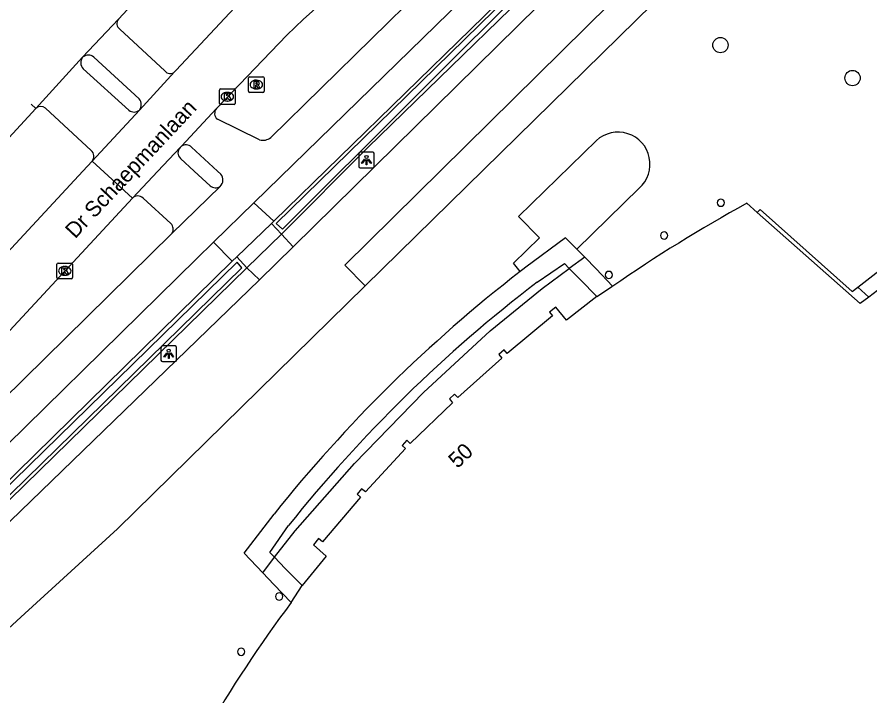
# Model space of a CAD drawing. Extents: x 161402 to 161933, y 381650 to 382313.
# Drawn here: x 161733.4 to 161787.9, y 382216.4 to 382259.8 of the extents above; entities that cross this region are included whole.
import ezdxf

# ---------------------------------------------------------------- set-up
doc = ezdxf.new("R2010")
doc.units = 0
for name, color, linetype in [('IMGEO_Boom', 7, 'Continuous'), ('IMGEO_Fietspad_open', 7, 'Continuous'), ('IMGEO_Kolk', 7, 'Continuous'), ('IMGEO_Lichtpunt', 7, 'Continuous'), ('IMGEO_Muur', 7, 'Continuous'), ('IMGEO_Openbare_ruimte_label', 7, 'Continuous'), ('IMGEO_Pand', 7, 'Continuous'), ('IMGEO_Pand_nummerreeks', 7, 'Continuous'), ('IMGEO_Rijbaan_lokaal_gesloten', 7, 'Continuous'), ('IMGEO_Rijbaan_lokaal_open', 7, 'Continuous'), ('IMGEO_Rioolput', 7, 'Continuous'), ('IMGEO_Voetpad_gesloten', 7, 'Continuous'), ('IMGEO_Voetpad_open', 7, 'Continuous')]:
    doc.layers.add(name, color=color, linetype=linetype)

msp = doc.modelspace()

# ---------------------------------------------------------------- linework, layer by layer
at = {"layer": 'IMGEO_Boom'}
for centre in [(161778.302, 382258.047), (161786.74, 382255.943)]:
    msp.add_circle(centre, 0.489, dxfattribs=at)
at = {"layer": 'IMGEO_Fietspad_open'}
for points in [[(161762.43, 382264.784), (161749.565, 382252.142)], [(161748.486, 382247.967), (161765.113, 382264.207)], [(161739.929, 382259.066), (161742.796, 382256.396)], [(161741.158, 382254.603), (161738.265, 382257.28)], [(161748.853, 382251.989), (161746.158, 382253.319)], [(161744.502, 382251.534), (161746.159, 382250), (161746.382, 382249.794)], [(161746.337, 382249.017), (161743.258, 382246.014)], [(161745.906, 382245.446), (161748.486, 382247.967)], [(161743.258, 382246.014), (161728.369, 382231.371), (161727.383, 382230.373), (161709.873, 382209.811)], [(161711.467, 382208.182), (161729.058, 382228.913), (161744.819, 382244.379), (161745.906, 382245.446)]]:
    msp.add_lwpolyline(points, dxfattribs=at)
for centre, radius, start, end in [((161740.169, 382259.426), 0.433, 140.7167, 236.3271), ((161737.915, 382256.852), 0.553, 50.7037, 131.3767), ((161743.142, 382256.687), 0.453, 220.082, 308.6592), ((161740.743, 382254.236), 0.555, 321.7237, 41.4988), ((161746.452, 382253.683), 0.468, 139.3618, 231.058), ((161749.059, 382252.765), 0.802, 255.1413, 309.1142), ((161744.154, 382251.15), 0.518, 47.7745, 123.7726), ((161745.956, 382249.429), 0.561, 312.7967, 40.5741)]:
    msp.add_arc(centre, radius, start, end, dxfattribs=at)
at = {"layer": 'IMGEO_Kolk'}
for p, q in [((161746.297, 382254.32), (161746.297, 382255.172)), ((161746.372, 382255.246), (161747.224, 382255.246)), ((161746.785, 382255.026), (161746.81, 382255.026)), ((161747.298, 382255.172), (161747.298, 382254.32)), ((161746.808, 382254.466), (161746.783, 382254.466)), ((161747.224, 382254.246), (161746.372, 382254.246)), ((161735.911, 382243.191), (161735.911, 382244.043)), ((161735.986, 382244.117), (161736.838, 382244.117)), ((161736.912, 382244.043), (161736.912, 382243.191)), ((161736.399, 382243.897), (161736.424, 382243.897)), ((161736.838, 382243.117), (161735.986, 382243.117)), ((161736.422, 382243.337), (161736.397, 382243.337))]:
    msp.add_line(p, q, dxfattribs=at)
for points in [[(161746.297, 382254.32), (161746.297, 382255.172)], [(161746.372, 382255.246), (161747.224, 382255.246)], [(161746.618, 382254.946), (161746.741, 382254.946), (161746.741, 382254.795), (161746.871, 382254.946), (161747.035, 382254.946), (161746.889, 382254.795), (161747.042, 382254.546), (161746.89, 382254.546), (161746.805, 382254.71), (161746.741, 382254.643), (161746.741, 382254.546), (161746.618, 382254.546), (161746.618, 382254.946)], [(161747.298, 382255.172), (161747.298, 382254.32)], [(161747.224, 382254.246), (161746.372, 382254.246)], [(161735.911, 382243.191), (161735.911, 382244.043)], [(161735.986, 382244.117), (161736.838, 382244.117)], [(161736.912, 382244.043), (161736.912, 382243.191)], [(161736.232, 382243.817), (161736.355, 382243.817), (161736.355, 382243.666), (161736.485, 382243.817), (161736.649, 382243.817), (161736.503, 382243.666), (161736.656, 382243.417), (161736.504, 382243.417), (161736.419, 382243.581), (161736.355, 382243.514), (161736.355, 382243.417), (161736.232, 382243.417), (161736.232, 382243.817)], [(161736.838, 382243.117), (161735.986, 382243.117)]]:
    msp.add_lwpolyline(points, dxfattribs=at)
for centre, start, end in [((161746.374, 382255.17), 91.552, 178.448), ((161746.374, 382255.17), 91.552, 178.448), ((161747.222, 382255.17), 1.552, 88.448), ((161747.222, 382255.17), 1.552, 88.448), ((161746.374, 382254.322), 181.552, 268.448), ((161746.374, 382254.322), 181.552, 268.448), ((161747.222, 382254.322), 271.552, 358.448), ((161747.222, 382254.322), 271.552, 358.448), ((161735.988, 382244.041), 91.552, 178.448), ((161735.988, 382244.041), 91.552, 178.448), ((161736.836, 382244.041), 1.552, 88.448), ((161736.836, 382244.041), 1.552, 88.448), ((161735.988, 382243.193), 181.552, 268.448), ((161735.988, 382243.193), 181.552, 268.448), ((161736.836, 382243.193), 271.552, 358.448), ((161736.836, 382243.193), 271.552, 358.448)]:
    msp.add_arc(centre, 0.0765, start, end, dxfattribs=at)
for centre, major_axis, ratio, start_param, end_param in [((161746.784, 382254.746), (-0.387, 0.002), 0.722429, 4.712389, 7.853982), ((161746.809, 382254.746), (-0.39, 0.002), 0.717154, 1.570796, 4.712389), ((161736.398, 382243.617), (-0.387, 0.002), 0.722429, 4.712389, 7.853982), ((161736.423, 382243.617), (-0.39, 0.002), 0.717154, 1.570796, 4.712389)]:
    msp.add_ellipse(centre, major_axis=major_axis, ratio=ratio, start_param=start_param, end_param=end_param, dxfattribs=at)
at = {"layer": 'IMGEO_Lichtpunt'}
for p, q in [((161755.191, 382251.099), (161755.191, 382250.292)), ((161755.191, 382251.099), (161755.191, 382250.292)), ((161756.093, 382251.194), (161755.285, 382251.194)), ((161756.093, 382251.194), (161755.285, 382251.194)), ((161756.187, 382250.292), (161756.187, 382251.099)), ((161756.187, 382250.292), (161756.187, 382251.099)), ((161755.285, 382250.198), (161756.093, 382250.198)), ((161755.285, 382250.198), (161756.093, 382250.198)), ((161742.554, 382238.724), (161742.554, 382237.917)), ((161742.554, 382238.724), (161742.554, 382237.917)), ((161743.456, 382238.819), (161742.648, 382238.819)), ((161743.456, 382238.819), (161742.648, 382238.819)), ((161743.55, 382237.917), (161743.55, 382238.724)), ((161743.55, 382237.917), (161743.55, 382238.724)), ((161742.648, 382237.823), (161743.456, 382237.823)), ((161742.648, 382237.823), (161743.456, 382237.823))]:
    msp.add_line(p, q, dxfattribs=at)
for points in [[(161755.565, 382250.763), (161755.604, 382250.735), (161755.416, 382250.473), (161755.378, 382250.5), (161755.565, 382250.763)], [(161755.667, 382250.715), (161755.714, 382250.715), (161755.714, 382250.393), (161755.667, 382250.393), (161755.667, 382250.715)], [(161755.777, 382250.735), (161755.815, 382250.762), (161756.002, 382250.5), (161755.963, 382250.472), (161755.777, 382250.735)], [(161742.928, 382238.388), (161742.967, 382238.36), (161742.779, 382238.098), (161742.741, 382238.125), (161742.928, 382238.388)], [(161743.03, 382238.34), (161743.077, 382238.34), (161743.077, 382238.018), (161743.03, 382238.018), (161743.03, 382238.34)], [(161743.14, 382238.36), (161743.178, 382238.387), (161743.365, 382238.125), (161743.326, 382238.097), (161743.14, 382238.36)]]:
    msp.add_lwpolyline(points, dxfattribs=at)
for centre in [(161755.69, 382250.897), (161743.053, 382238.522)]:
    msp.add_circle(centre, 0.0994, dxfattribs=at)
for centre, start, end in [((161755.285, 382251.099), 90, 180), ((161755.285, 382251.099), 90, 180), ((161756.093, 382251.099), 0, 90), ((161756.093, 382251.099), 0, 90), ((161755.285, 382250.292), 180, 270), ((161755.285, 382250.292), 180, 270), ((161756.093, 382250.292), 270, 0), ((161756.093, 382250.292), 270, 360), ((161742.648, 382238.724), 90, 180), ((161742.648, 382238.724), 90, 180), ((161743.456, 382238.724), 0, 90), ((161743.456, 382238.724), 0, 90), ((161742.648, 382237.917), 180, 270), ((161742.648, 382237.917), 180, 270), ((161743.456, 382237.917), 270, 0), ((161743.456, 382237.917), 270, 360)]:
    msp.add_arc(centre, 0.0946, start, end, dxfattribs=at)
at = {"layer": 'IMGEO_Muur'}
for points in [[(161749.768, 382246.799), (161766.553, 382263.178), (161766.895, 382262.953), (161769.85, 382265.834), (161770.184, 382265.542), (161755.779, 382251.492), (161750.251, 382245.958)], [(161750.317, 382246.283), (161766.834, 382262.773), (161766.612, 382262.991), (161749.919, 382246.636), (161750.317, 382246.283)], [(161749.616, 382246.65), (161749.768, 382246.799)], [(161750.251, 382245.958), (161749.616, 382246.65)], [(161747.1, 382244.24), (161747.399, 382244.517)], [(161747.399, 382244.517), (161748.046, 382243.815)], [(161748.046, 382243.815), (161715.85, 382212.342), (161715.57, 382212.632), (161719.892, 382216.863), (161719.584, 382217.248), (161747.1, 382244.24)], [(161720.173, 382216.864), (161747.726, 382243.82), (161747.429, 382244.182), (161719.85, 382217.217), (161720.173, 382216.864)]]:
    msp.add_lwpolyline(points, dxfattribs=at)
at = {"layer": 'IMGEO_Pand'}
for points in [[(161779.989, 382247.938), (161780.646, 382247.356)], [(161787.788, 382241.947), (161787.231, 382241.522), (161780.646, 382247.356)], [(161795.694, 382238.808), (161794.961, 382238.384), (161795.219, 382237.93), (161794.18, 382236.915), (161789.097, 382243.778), (161788.496, 382243.19), (161788.889, 382242.788), (161787.788, 382241.947)], [(161770.405, 382241.973), (161771.415, 382242.629)], [(161770.405, 382241.973), (161768.459, 382240.475), (161767.778, 382241.294), (161767.375, 382240.978), (161767.578, 382240.738), (161764.683, 382238.344), (161764.488, 382238.566), (161764.134, 382238.278), (161764.331, 382238.028), (161761.527, 382235.526), (161761.314, 382235.737), (161760.988, 382235.435), (161761.183, 382235.183), (161758.474, 382232.588), (161758.255, 382232.795), (161757.969, 382232.452), (161758.183, 382232.257), (161755.627, 382229.489), (161755.369, 382229.691), (161755.085, 382229.339), (161755.299, 382229.159), (161752.877, 382226.292), (161752.611, 382226.516), (161752.291, 382226.105), (161753.12, 382225.389), (161751.568, 382223.506)], [(161750.883, 382222.424), (161751.568, 382223.506)]]:
    msp.add_lwpolyline(points, dxfattribs=at)
for centre, radius, start, end in [((161825.854, 382164.289), 95.398, 118.73588, 124.7955), ((161778.325, 382247.974), 0.23, 90, 270), ((161778.325, 382247.974), 0.23, 270, 90), ((161774.702, 382245.879), 0.23, 90, 270), ((161774.702, 382245.879), 0.23, 270, 90), ((161771.17, 382243.355), 0.23, 90, 270), ((161771.17, 382243.355), 0.23, 270, 90), ((161750.105, 382222.803), 0.23, 90, 270), ((161750.105, 382222.803), 0.23, 270, 90), ((161816.968, 382172.845), 82.616, 143.12172, 150.09585), ((161747.682, 382219.274), 0.23, 90, 270), ((161747.682, 382219.274), 0.23, 270, 90)]:
    msp.add_arc(centre, radius, start, end, dxfattribs=at)
at = {"layer": 'IMGEO_Rijbaan_lokaal_gesloten'}
for points in [[(161739.834, 382259.7), (161744.067, 382264.267), (161744.269, 382264.464)], [(161747.864, 382261.109), (161743.521, 382256.439), (161743.425, 382256.334)], [(161737.549, 382257.267), (161739.834, 382259.7)], [(161734.565, 382254.001), (161737.549, 382257.267)], [(161746.097, 382253.988), (161749.055, 382257.09)], [(161743.425, 382256.334), (161741.178, 382253.892)], [(161697.412, 382213.802), (161730.864, 382250), (161734.565, 382254.001)], [(161734.565, 382254.001), (161734.265, 382254.268)], [(161741.178, 382253.892), (161738.153, 382250.632)], [(161743.866, 382251.581), (161746.097, 382253.988)], [(161740.731, 382248.263), (161742.363, 382250), (161743.776, 382251.504)], [(161743.776, 382251.504), (161743.866, 382251.581)], [(161738.153, 382250.632), (161737.568, 382250), (161701.048, 382210.574)], [(161738.153, 382250.632), (161740.731, 382248.263)], [(161709.017, 382214.078), (161740.731, 382248.263)]]:
    msp.add_lwpolyline(points, dxfattribs=at)
msp.add_arc((161792.83, 382215.895), 60.111, 114.26707, 136.73891, dxfattribs=at)
at = {"layer": 'IMGEO_Rijbaan_lokaal_open'}
for points in [[(161777.222, 382263.881), (161775.857, 382265.264), (161754.297, 382243.989), (161755.602, 382242.666)], [(161766.659, 382260.549), (161751.001, 382245.149)], [(161751.001, 382245.149), (161748.845, 382243.038)], [(161748.845, 382243.038), (161728.253, 382223.117), (161713.169, 382208.748), (161711.914, 382207.765)], [(161755.602, 382242.666), (161739.772, 382227.133), (161733.859, 382221.725), (161710.972, 382200.713)]]:
    msp.add_lwpolyline(points, dxfattribs=at)
at = {"layer": 'IMGEO_Rioolput'}
for p, q in [((161748.145, 382255.099), (161748.145, 382255.951)), ((161748.22, 382256.025), (161749.072, 382256.025)), ((161749.146, 382255.951), (161749.146, 382255.099)), ((161748.633, 382255.805), (161748.658, 382255.805)), ((161749.072, 382255.025), (161748.22, 382255.025)), ((161748.656, 382255.245), (161748.631, 382255.245))]:
    msp.add_line(p, q, dxfattribs=at)
for points in [[(161748.145, 382255.099), (161748.145, 382255.951)], [(161748.22, 382256.025), (161749.072, 382256.025)], [(161749.146, 382255.951), (161749.146, 382255.099)], [(161748.734, 382255.723), (161748.482, 382255.725), (161748.482, 382255.325)], [(161748.482, 382255.325), (161748.606, 382255.325), (161748.606, 382255.487), (161748.617, 382255.487)], [(161748.66, 382255.644), (161748.606, 382255.644), (161748.606, 382255.563)], [(161748.606, 382255.563), (161748.658, 382255.563)], [(161748.664, 382255.458), (161748.735, 382255.325), (161748.875, 382255.325), (161748.81, 382255.451)], [(161749.072, 382255.025), (161748.22, 382255.025)]]:
    msp.add_lwpolyline(points, dxfattribs=at)
for centre, radius, start, end in [((161748.222, 382255.949), 0.0765, 91.552, 178.448), ((161748.222, 382255.949), 0.0765, 91.552, 178.448), ((161749.07, 382255.949), 0.0765, 1.552, 88.448), ((161749.07, 382255.949), 0.0765, 1.552, 88.448), ((161748.616, 382255.434), 0.0533, 26.0293, 88.6989), ((161748.642, 382255.752), 0.19, 274.7715, 282.9687), ((161748.666, 382255.548), 0.0964, 77.0061, 93.1865), ((161748.68, 382255.605), 0.0378, 276.6634, 79.6772), ((161748.733, 382255.613), 0.109, 350.3612, 89.416), ((161748.731, 382255.613), 0.112, 277.5842, 350.9817), ((161748.715, 382255.398), 0.108, 29.5134, 73.7905), ((161748.222, 382255.101), 0.0765, 181.552, 268.448), ((161748.222, 382255.101), 0.0765, 181.552, 268.448), ((161749.07, 382255.101), 0.0765, 271.552, 358.448), ((161749.07, 382255.101), 0.0765, 271.552, 358.448)]:
    msp.add_arc(centre, radius, start, end, dxfattribs=at)
for centre, major_axis, ratio, start_param, end_param in [((161748.632, 382255.525), (-0.387, 0.002), 0.722429, 4.712389, 7.853982), ((161748.657, 382255.525), (-0.39, 0.002), 0.717154, 1.570796, 4.712389)]:
    msp.add_ellipse(centre, major_axis=major_axis, ratio=ratio, start_param=start_param, end_param=end_param, dxfattribs=at)
at = {"layer": 'IMGEO_Voetpad_gesloten'}
for points in [[(161765.497, 382243.567), (161765.071, 382244.108), (161766.74, 382245.739), (161765.399, 382247.095), (161770.372, 382251.939)], [(161773.106, 382248.909), (161769.121, 382245.01)], [(161747.399, 382244.517), (161749.616, 382246.65)], [(161748.046, 382243.815), (161750.251, 382245.958)], [(161769.121, 382245.01), (161768.404, 382245.728), (161765.872, 382243.856), (161765.684, 382243.712), (161765.497, 382243.567)], [(161769.121, 382245.01), (161769.36, 382244.771), (161769.63, 382244.495)], [(161766.598, 382242.904), (161768.328, 382244.084), (161768.633, 382243.777)], [(161769.63, 382244.495), (161768.633, 382243.777)], [(161769.63, 382244.495), (161770.365, 382243.746), (161771.415, 382242.629)], [(161768.633, 382243.777), (161769.339, 382243.065), (161770.405, 382241.973)], [(161749.059, 382224.31), (161747.869, 382225.581), (161749.786, 382228.073)], [(161749.811, 382225.312), (161749.515, 382225.622), (161750.706, 382227.341)], [(161749.059, 382224.31), (161749.811, 382225.312)], [(161751.568, 382223.506), (161750.499, 382224.592), (161749.811, 382225.312)], [(161750.883, 382222.424), (161749.77, 382223.583), (161749.059, 382224.31)]]:
    msp.add_lwpolyline(points, dxfattribs=at)
for centre, radius, start, end in [((161771.758, 382250.441), 2.041, 311.3489, 132.7717), ((161822.012, 382170.548), 92.335, 127.73907, 141.46407), ((161822.256, 382170.174), 91.583, 127.42564, 141.37584)]:
    msp.add_arc(centre, radius, start, end, dxfattribs=at)
at = {"layer": 'IMGEO_Voetpad_open'}
for points in [[(161777.222, 382263.881), (161755.602, 382242.666)], [(161737.59, 382256.54), (161740.5, 382253.884)], [(161738.093, 382251.314), (161735.183, 382254.02)], [(161743.794, 382250.802), (161744.671, 382250), (161745.696, 382249.062)], [(161743.193, 382246.637), (161741.415, 382248.269)], [(161748.486, 382247.967), (161749.768, 382246.799)], [(161780.646, 382247.356), (161780.83, 382247.541), (161786.714, 382242.292), (161787.078, 382242.574)], [(161750.251, 382245.958), (161751.001, 382245.149)], [(161747.1, 382244.24), (161745.906, 382245.446)], [(161787.078, 382242.574), (161789.189, 382244.207), (161793.608, 382238.098), (161795.702, 382239.34), (161795.946, 382238.964), (161796.112, 382238.709)], [(161748.845, 382243.038), (161748.046, 382243.815)], [(161749.811, 382225.312), (161751.13, 382227.004), (161754.914, 382231.309), (161759.32, 382235.852), (161763.589, 382239.792), (161766.914, 382242.49), (161768.633, 382243.777)], [(161787.078, 382242.574), (161787.788, 382241.947)]]:
    msp.add_lwpolyline(points, dxfattribs=at)
for centre, radius, start, end in [((161737.97, 382256.926), 0.541, 140.9693, 225.4864), ((161734.885, 382253.663), 0.465, 50.1176, 133.4044), ((161740.834, 382254.302), 0.535, 231.3877, 309.9644), ((161737.801, 382250.945), 0.471, 318.3858, 51.6697), ((161744.144, 382251.162), 0.502, 137.1337, 225.8039), ((161746.043, 382249.422), 0.5, 226.0253, 305.9432), ((161741.076, 382247.935), 0.476, 44.5516, 136.4535), ((161742.855, 382246.287), 0.487, 325.9277, 45.985)]:
    msp.add_arc(centre, radius, start, end, dxfattribs=at)

# ---------------------------------------------------------------- texts
at = {"layer": 'IMGEO_Openbare_ruimte_label'}
msp.add_text('Dr Schaepmanlaan', height=1, rotation=46.8241, dxfattribs=at).set_placement((161737.071, 382245.63))
at = {"layer": 'IMGEO_Pand_nummerreeks'}
msp.add_text('50', height=1, rotation=43.7687, dxfattribs=at).set_placement((161761.503, 382230.947))

doc.saveas('drawing.dxf')
